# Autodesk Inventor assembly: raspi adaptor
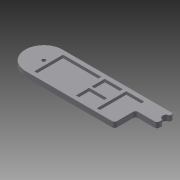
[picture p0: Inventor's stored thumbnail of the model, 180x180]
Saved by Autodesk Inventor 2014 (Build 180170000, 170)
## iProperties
Created: 2015-01
Part Number: raspi adaptor
Document SubType Name: Assembly
Designer: Drano
Author: Drano
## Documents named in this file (3)
- C:\Users\Drano\Documents\SD swiss army\raspi adaptor.iam
- C:\Users\Drano\Documents\SD swiss army\backplate.ipt
- C:\Users\Drano\Documents\SD swiss army\1XSD-2XMicroSD-1XRaspiAdaptor.ipt
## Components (2 placed, 2 different names)
1. backplate:1 — Mate:1, Mate:2, Flush:1
2. 1XSD-2XMicroSD-1XRaspiAdaptor:1 — Mate:1, Mate:2, Flush:1
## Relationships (3: Mate 2, Flush 1)
- Mate:1: backplate:1 ↔ 1XSD-2XMicroSD-1XRaspiAdaptor:1
- Mate:2: backplate:1 ↔ 1XSD-2XMicroSD-1XRaspiAdaptor:1
- Flush:1: backplate:1 ↔ 1XSD-2XMicroSD-1XRaspiAdaptor:1
